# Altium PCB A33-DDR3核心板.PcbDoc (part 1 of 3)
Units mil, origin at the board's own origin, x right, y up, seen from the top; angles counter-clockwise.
Board outline 2370 x 2515 mil, 4 copper layers (TOP, GND02, PWR03, BOTTOM), stack 38.4 mil thick; 39 components, 64 nets, 546 pads, 403 vias.
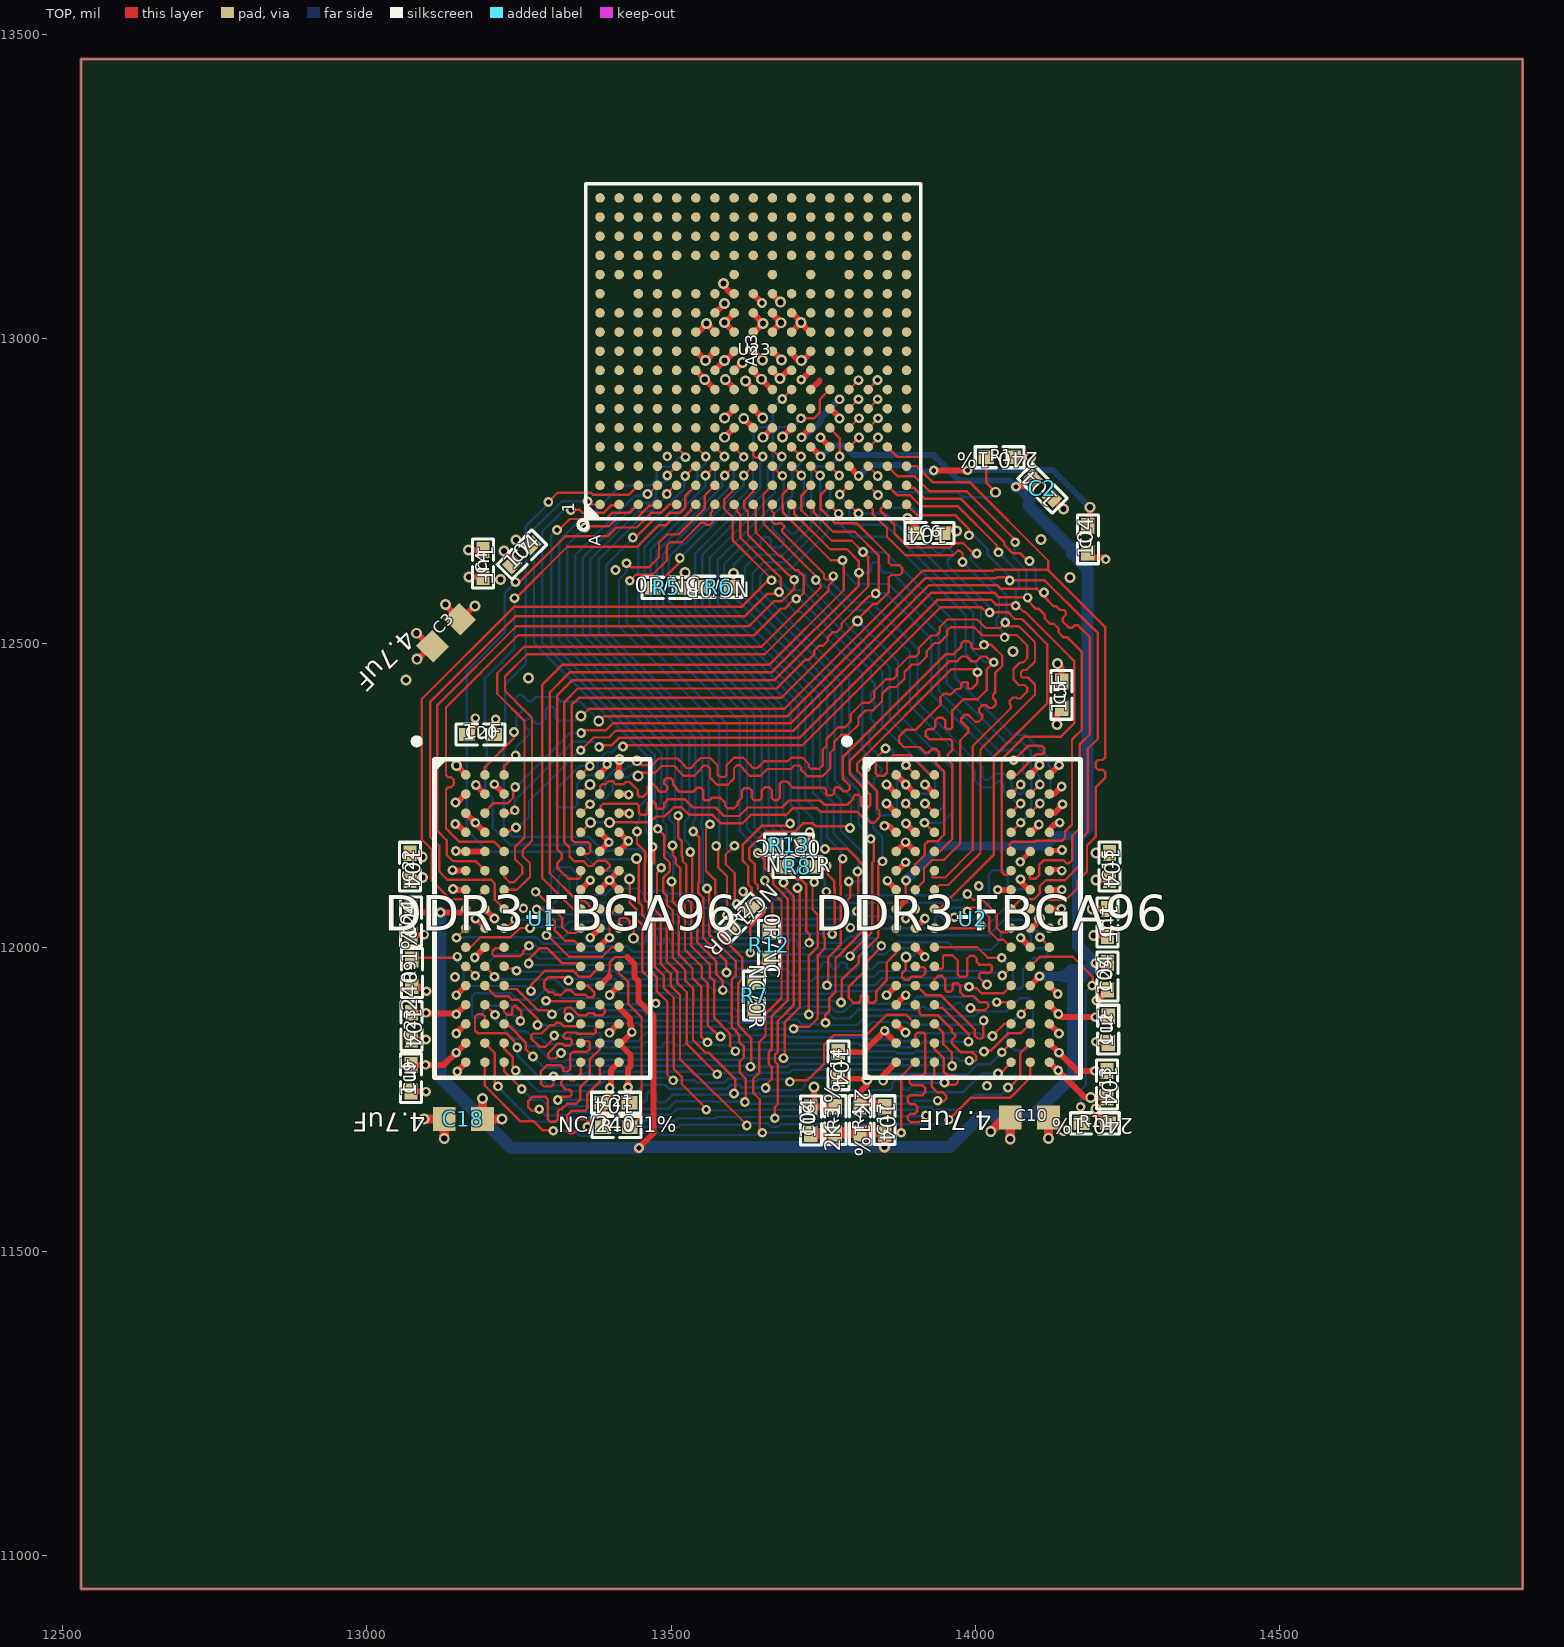
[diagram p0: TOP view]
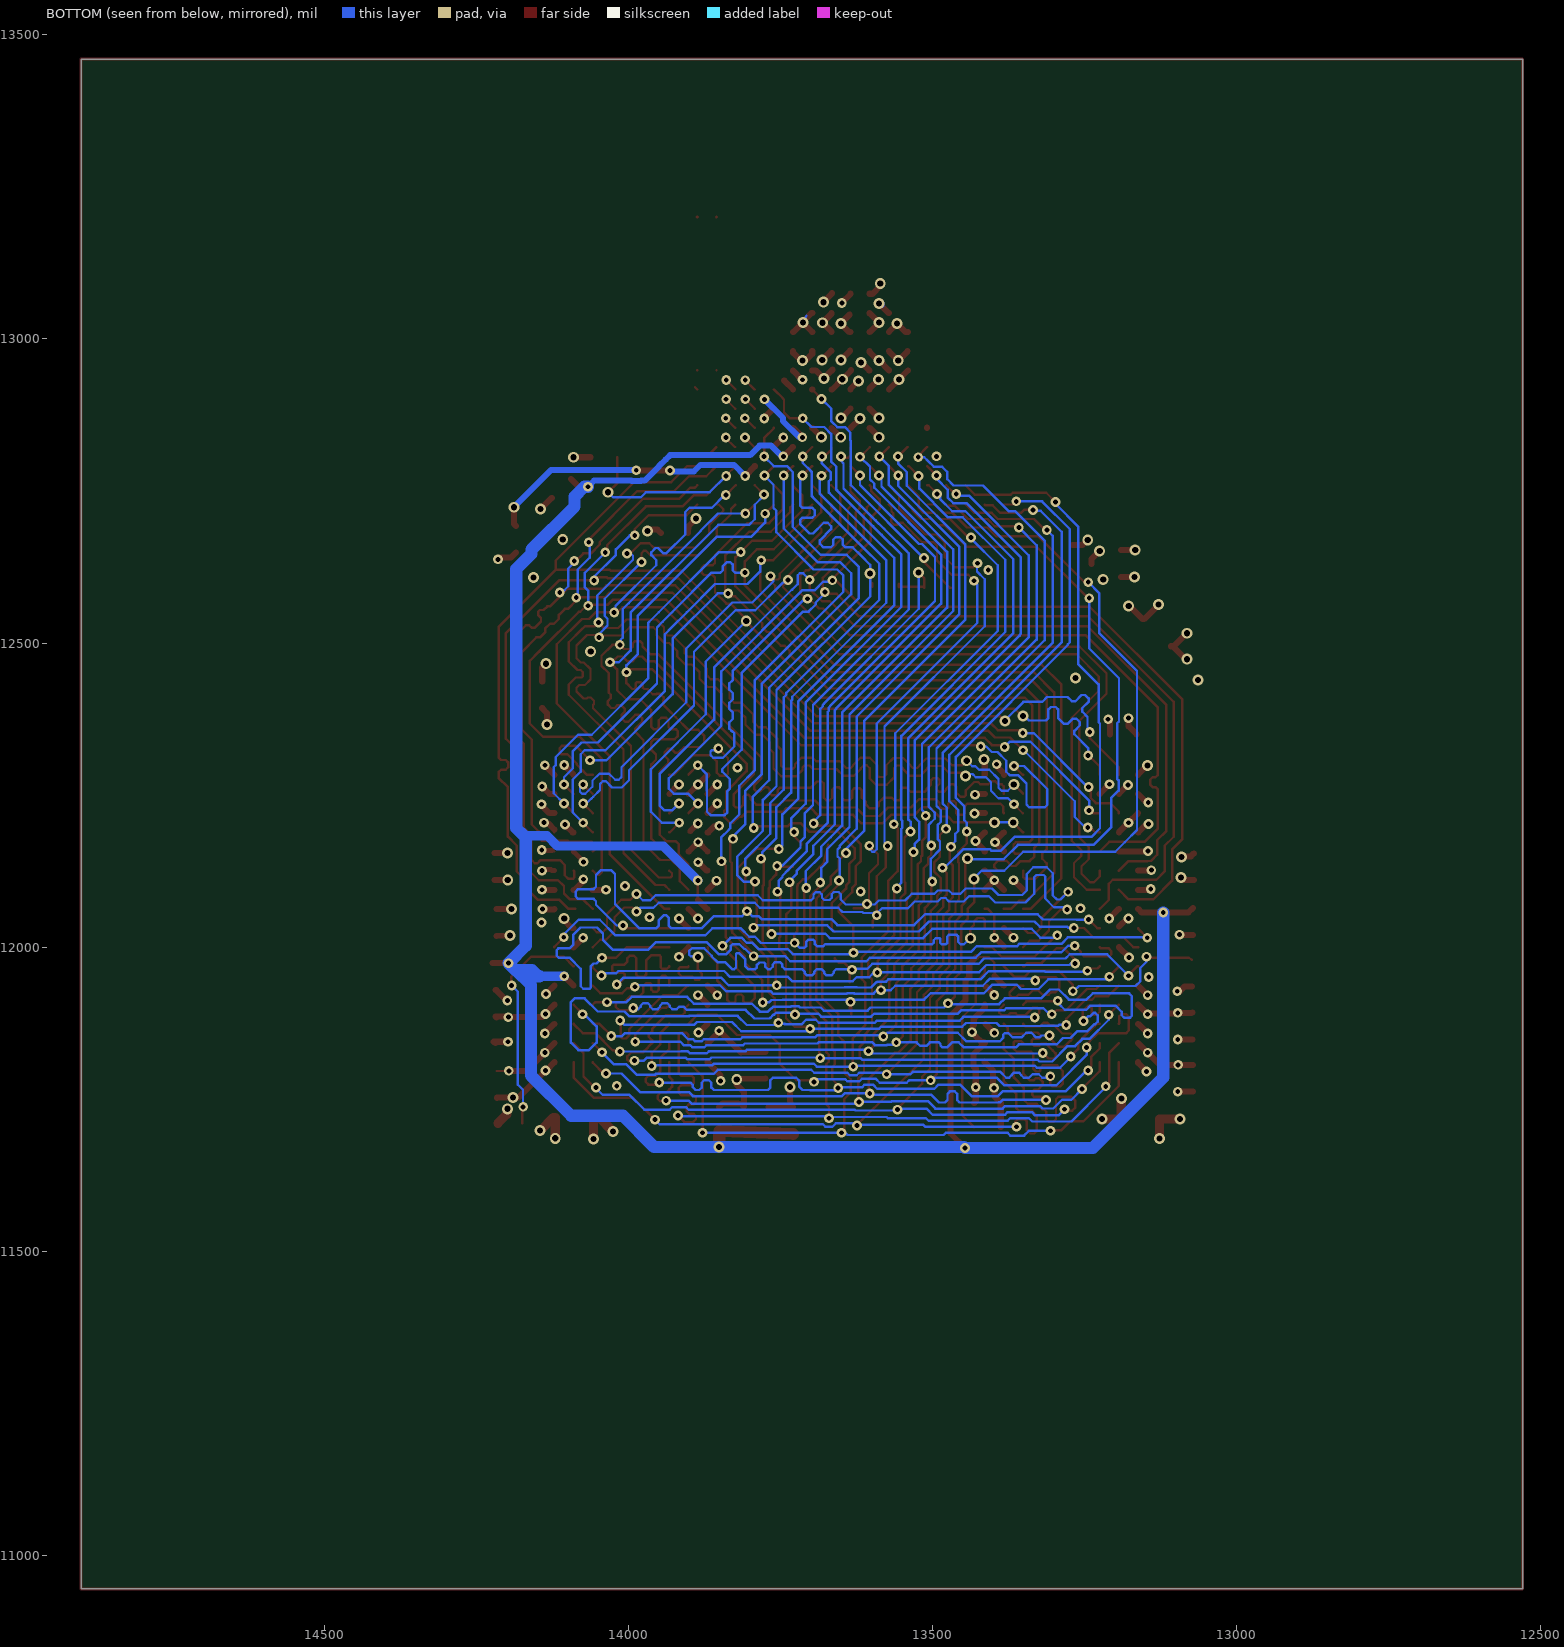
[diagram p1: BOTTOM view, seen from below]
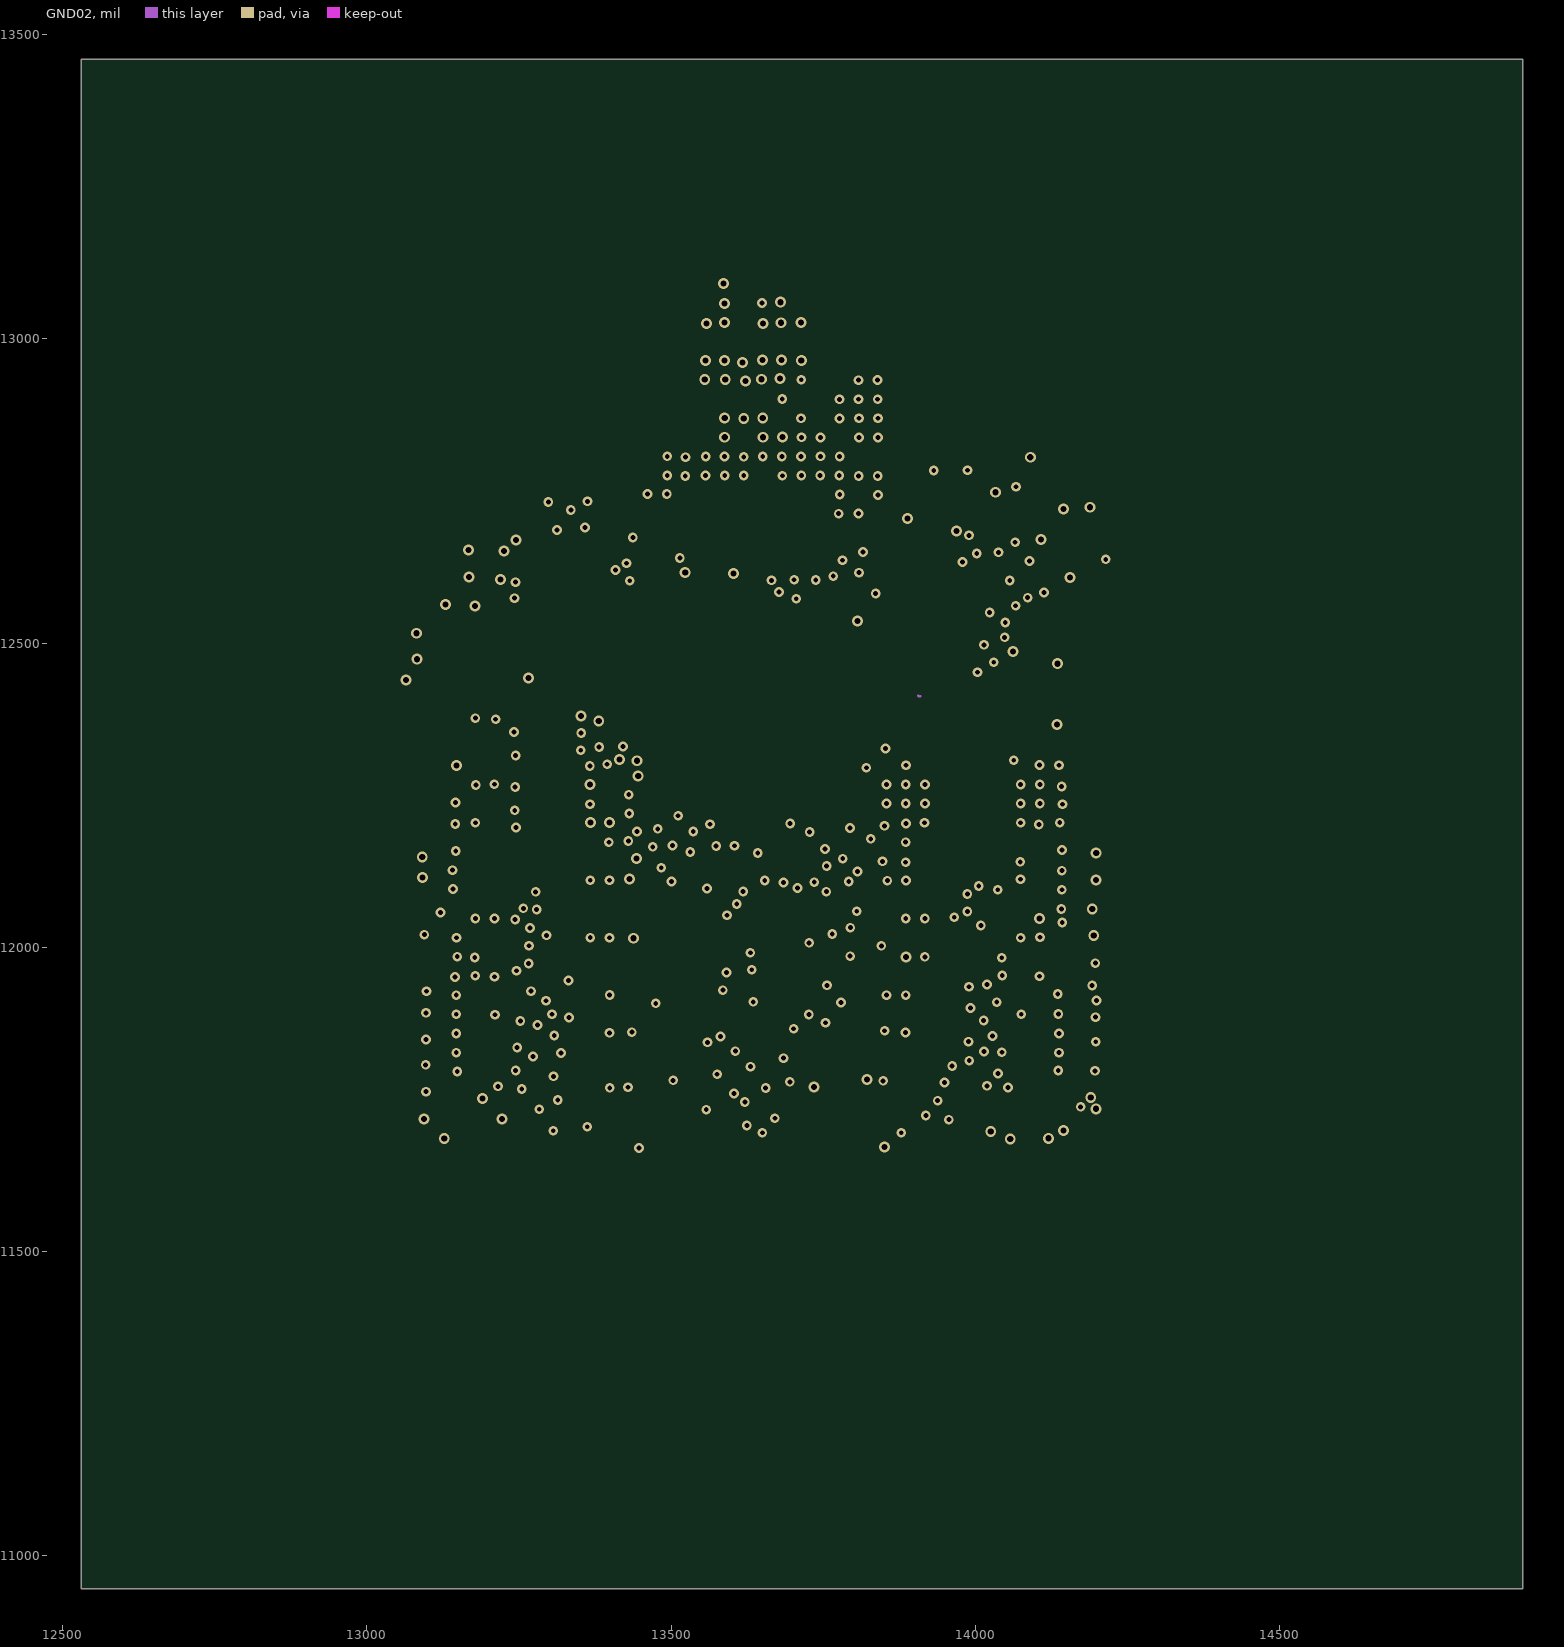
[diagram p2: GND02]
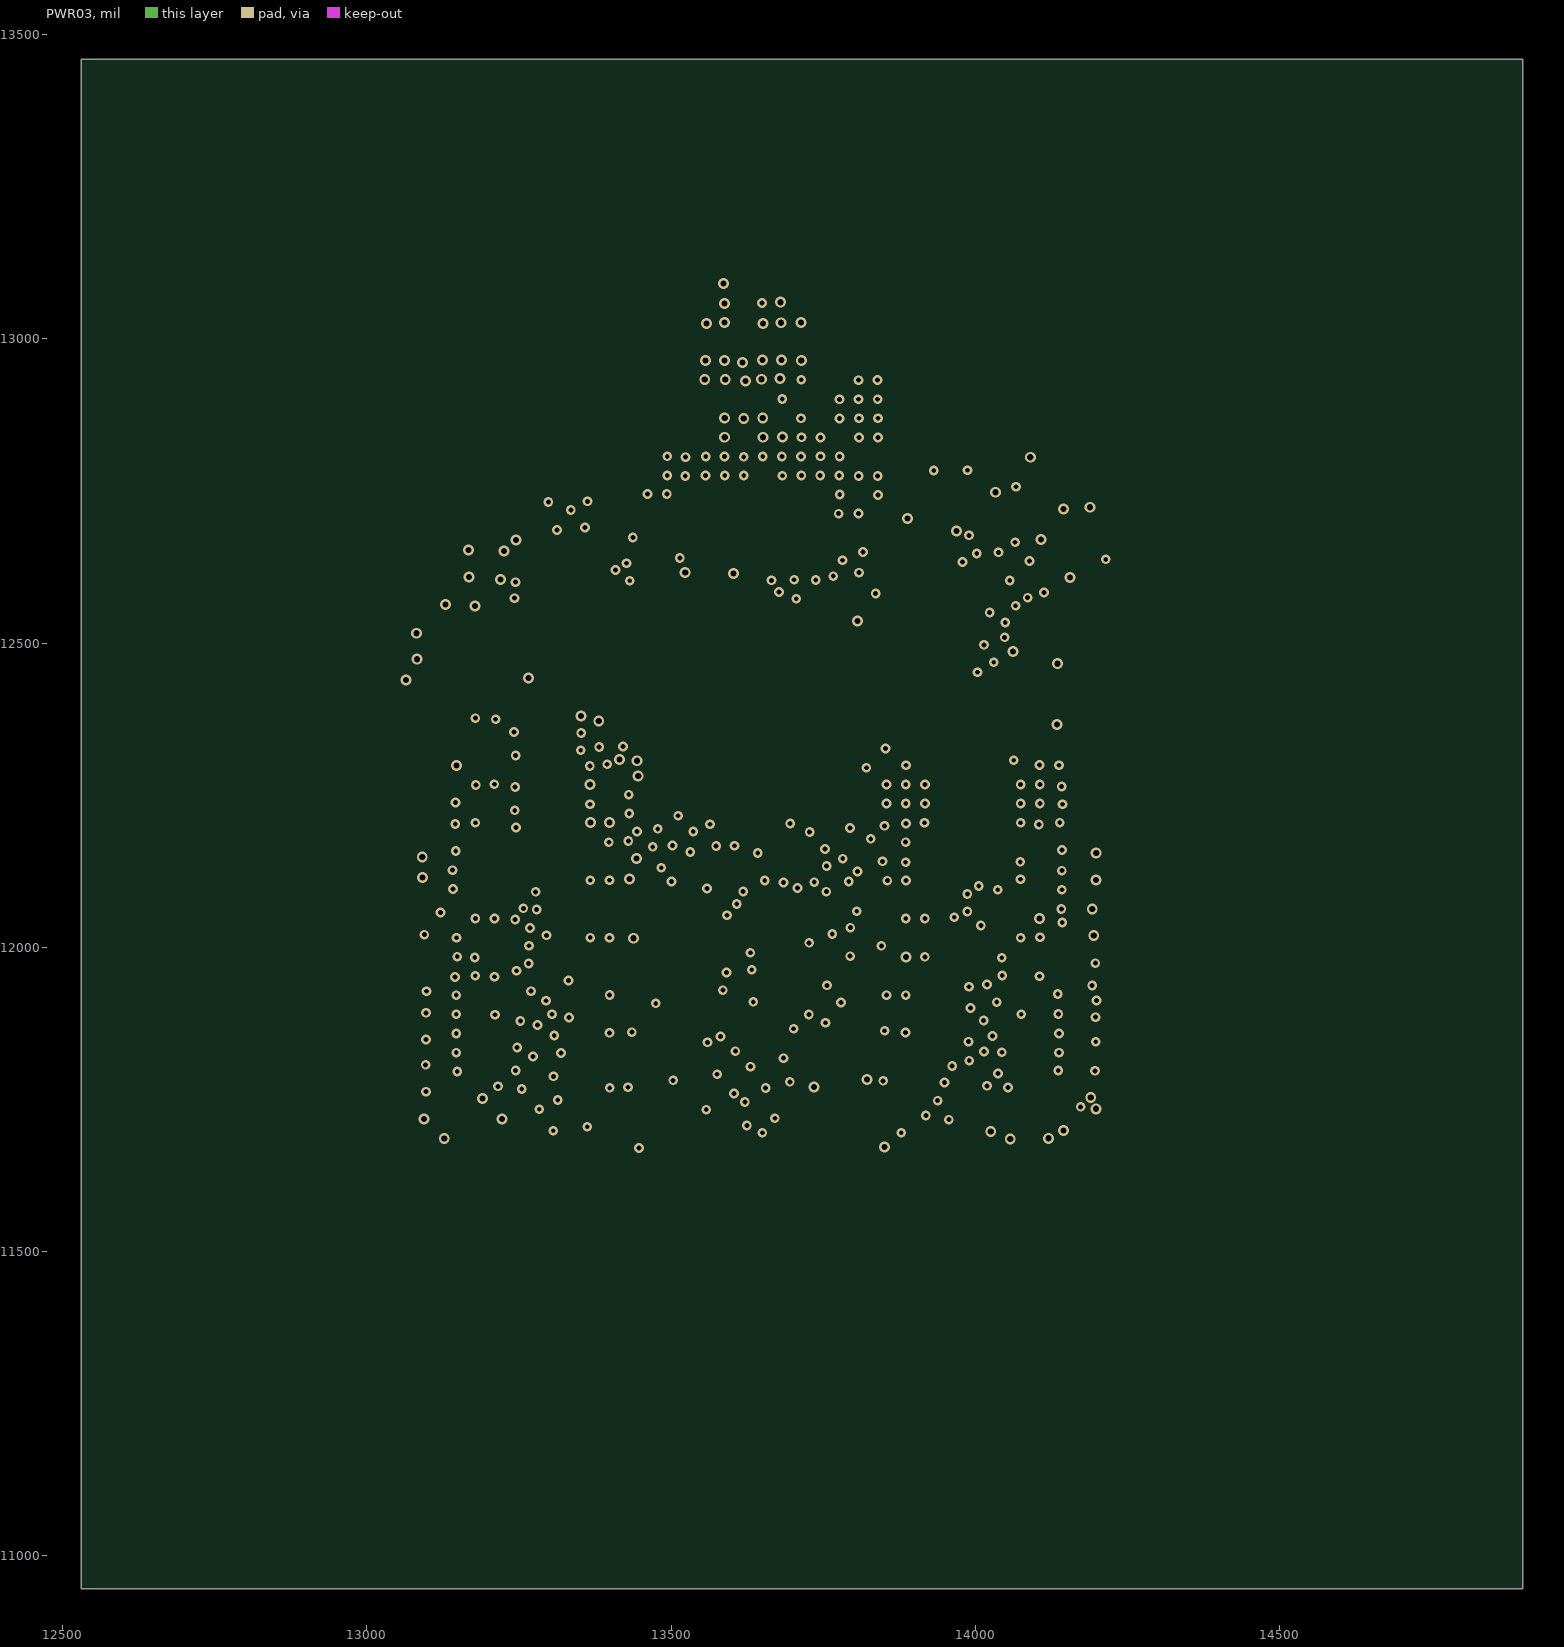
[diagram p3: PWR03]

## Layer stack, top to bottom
TOP: signal copper 1.6
Dielectric: core 2.9, FR-4, Dk 4.5
GND02: signal copper 1.2
Dielectric: core 27, FR-4, Dk 4.5
PWR03: signal copper 1.2
Dielectric: core 2.9, FR-4, Dk 4.5
BOTTOM: signal copper 1.6

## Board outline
12530,10945 12530,13460 14900,13460 14900,10945

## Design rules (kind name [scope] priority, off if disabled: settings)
Clearance [All] p1: gap=10
PlaneConnect [All] p1: planeconnectstyle=Direct reliefexpansion=20 reliefentries=4 reliefconductorwidth=10 reliefairgap=10
PolygonConnect [All] p1: connectstyle=Direct reliefconductorwidth=10 reliefentries=4 polygonreliefangle="90 Angle"
RoutingVias [All] p1: holewidth=28 width=50 viastyle="Through Hole" minholewidth=28 minwidth=50 maxholewidth=28 maxwidth=50
SilkscreenOverComponentPads SilkToSolderMaskClearance [IsPad] p1: minsilkscreentomaskgap=10
SolderMaskExpansion [All] p1: expansion=4
Width [All] p1: maxlimit=10 minlimit=10 preferedwidth=10 impedancedriven=TRUE minimp=2.160000 maximp=48.440000 favimp=2.060000
26 further rules are at their usual default settings.

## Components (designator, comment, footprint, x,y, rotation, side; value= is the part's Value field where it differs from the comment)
C1 "CAPACITOR_0_C0402_104" C0402 14185.25,12670.55 r90 top
C2 "CAPACITOR_0_C0402_104" C0402 14110.49,12754.23 r135 top
C3 "CAPACITOR_0_C0603_4.7UF" C0603 13130.2,12516.98 r225 top
C4 "CAPACITOR_0_C0402_1UF" C0402 13190.73,12630.78 r270 top
C5 "CAPACITOR_0_C0402_1UF" C0402 14141.93,12414.87 r90 top
C6 "CAPACITOR_0_C0402_104" C0402 13924.63,12680.77 r180 top
C7 "CAPACITOR_0_C0402_104" C0402 13254.63,12645.41 r45 top
C10 "CAPACITOR_0_C0603_4.7UF" C0603 14089.03,11720.11 r180 top
C11 "CAPACITOR_0_C0402_1UF" C0402 14217.37,12040.59 r270 top
C12 "CAPACITOR_0_C0402_1UF" C0402 14218.69,11864.32 r90 top
C13 "CAP_0_C0402_104" C0402 14216.52,11774.39 r270 top
C14 "CAP_0_C0402_104" C0402 13775.06,11805.81 r270 top
C15 "CAP_0_C0402_104" C0402 14220.62,12132.68 r270 top
C16 "CAPACITOR_0_C0402_104" C0402 13729.74,11714.88 r90 top
C17 "CAPACITOR_0_C0402_104" C0402 13851.01,11715.57 r270 top
C18 "CAPACITOR_0_C0603_4.7UF" C0603 13158.49,11717.8 r180 top
C19 "CAPACITOR_0_C0402_1UF" C0402 13072.42,11784.51 r90 top
C20 "CAPACITOR_0_C0402_1UF" C0402 13186.65,12349.73 r0 top
C21 "CAP_0_C0402_104" C0402 13409.35,11744.2 r180 top
C22 "CAP_0_C0402_104" C0402 13070.7,12132.27 r270 top
C23 "CAP_0_C0402_104" C0402 13073.14,11870.3 r270 top
C24 "CAPACITOR_0_C0402_104" C0402 13072.35,12042.25 r90 top
C25 "CAPACITOR_0_C0402_104" C0402 14217.33,11951.85 r90 top
R1 "R_R0402_240-1%" R0402 14040.23,12805.45 r180 top
R2 "R1 0805_R0402_NC/100R" R0402 13614.28,12048.28 r225 top
R3 "?_0_R0402_2K-1%" R0402 13769.95,11715.57 r90 top
R4 "?_0_R0402_2K-1%" R0402 13810.48,11715.91 r270 top
R5 "R1 0805_R0402_0R/NC" R0402 13492.2,12590.8 r0 top
R6 "R1 0805_R0402_NC/0R" R0402 13577.1,12592.54 r180 top
R7 "R1 0805_R0402_NC/0R" R0402 13636.45,11920.25 r270 top
R8 "R1 0805_R0402_NC/0R" R0402 13707.74,12131.95 r0 top
R9 "R_R0402_240-1%" R0402 13073.82,11957.62 r90 top
R10 "R_R0402_NC/240-1%" R0402 13410.09,11704.12 r0 top
R11 "R_R0402_240-1%" R0402 14196.47,11710.43 r180 top
R12 "R1 0805_R0402_0R/NC" R0402 13661.2,12003.64 r270 top
R13 "R1 0805_R0402_0R/NC" R0402 13694.03,12168.45 r180 top
U1 "DDR3_1_FBGA96C80P9X13_DDR3-FBGA" FBGA96C80P9X13 13288.36,12047.08 r0 top
U2 "DDR3_1_FBGA96C80P9X13_DDR3-FBGA" FBGA96C80P9X13 13995.92,12047.09 r0 top
U23 "BGA280_3_BGA282P0_80B14X14H1_30" BGA282P0_80B14X14H1_30 13635.26,12979.4 r90 top

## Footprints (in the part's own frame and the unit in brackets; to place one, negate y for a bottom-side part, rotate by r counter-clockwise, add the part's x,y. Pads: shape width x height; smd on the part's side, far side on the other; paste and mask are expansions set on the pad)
BGA282P0_80B14X14H1_30 [mm] "BGA282P0_80B14X14H1_30"
  round 0.4 smd: A1(-6.39,6.405) A2(-5.59,6.405) A3(-4.79,6.405) A4(-3.99,6.405) A5(-3.19,6.405) A6(-2.39,6.405) A7(-1.59,6.405) A8(-0.79,6.405) A9(0.01,6.405) A10(0.81,6.405) A11(1.61,6.405) A12(2.41,6.405) A13(3.21,6.405) A14(4.01,6.405) A15(4.81,6.405) A16(5.61,6.405) A17(6.41,6.405) B1(-6.39,5.605) B2(-5.59,5.605) B3(-4.79,5.605) B4(-3.99,5.605) B5(-3.19,5.605) B6(-2.39,5.605) B7(-1.59,5.605) B8(-0.79,5.605) B9(0.01,5.605) B10(0.81,5.605) B11(1.61,5.605) B13(3.21,5.605) B14(4.01,5.605) B15(4.81,5.605) B16(5.61,5.605) B17(6.41,5.605) C1(-6.39,4.805) C2(-5.59,4.805) C3(-4.79,4.805) C4(-3.99,4.805) C5(-3.19,4.805) C6(-2.39,4.805) C7(-1.59,4.805) C8(-0.79,4.805) C9(0.01,4.805) C10(0.81,4.805) C11(1.61,4.805) C12(2.41,4.805) C13(3.21,4.805) C14(4.01,4.805) C15(4.81,4.805) C16(5.61,4.805) C17(6.41,4.805) D1(-6.39,4.005) D2(-5.59,4.005) D3(-4.79,4.005) D4(-3.99,4.005) D5(-3.19,4.005) D6(-2.39,4.005) D7(-1.59,4.005) D8(-0.79,4.005) D9(0.01,4.005) D10(0.81,4.005) D11(1.61,4.005) D12(2.41,4.005) D13(3.21,4.005) D14(4.01,4.005) D15(4.81,4.005) D16(5.61,4.005) D17(6.41,4.005) E1(-6.39,3.205) E2(-5.59,3.205) E3(-4.79,3.205) E4(-3.99,3.205) E5(-3.19,3.205) E6(-2.39,3.205) E7(-1.59,3.205) E8(-0.79,3.205) E9(0.01,3.205) E10(0.81,3.205) E11(1.61,3.205) E12(2.41,3.205) E14(4.01,3.205) E15(4.81,3.205) E16(5.61,3.205) E17(6.41,3.205) F1(-6.39,2.405) F2(-5.59,2.405) F3(-4.79,2.405) F4(-3.99,2.405) F5(-3.19,2.405) F6(-2.39,2.405) F7(-1.59,2.405) F8(-0.79,2.405) F9(0.01,2.405) F10(0.81,2.405) F11(1.61,2.405) F12(2.41,2.405) F14(4.01,2.405) F15(4.81,2.405) F16(5.61,2.405) F17(6.41,2.405) G1(-6.39,1.605) G2(-5.59,1.605) G3(-4.79,1.605) G4(-3.99,1.605) G5(-3.19,1.605) G6(-2.39,1.605) G7(-1.59,1.605) G8(-0.79,1.605) G9(0.01,1.605) G10(0.81,1.605) G11(1.61,1.605) G12(2.41,1.605) G14(4.01,1.605) G15(4.81,1.605) G16(5.61,1.605) G17(6.41,1.605) H1(-6.39,0.805) H2(-5.59,0.805) H3(-4.79,0.805) H4(-3.99,0.805) H5(-3.19,0.805) H6(-2.39,0.805) H7(-1.59,0.805) H8(-0.79,0.805) H9(0.01,0.805) H10(0.81,0.805) H11(1.61,0.805) H12(2.41,0.805) H13(3.21,0.805) H14(4.01,0.805) H15(4.81,0.805) H16(5.61,0.805) H17(6.41,0.805) J1(-6.39,0.005) J2(-5.59,0.005) J3(-4.79,0.005) J4(-3.99,0.005) J5(-3.19,0.005) J6(-2.39,0.005) J7(-1.59,0.005) J8(-0.79,0.005) J9(0.01,0.005) J10(0.81,0.005) J11(1.61,0.005) J12(2.41,0.005) J14(4.01,0.005) J15(4.81,0.005) J16(5.61,0.005) J17(6.41,0.005) K1(-6.39,-0.795) K2(-5.59,-0.795) K3(-4.79,-0.795) K4(-3.99,-0.795) K5(-3.19,-0.795) K6(-2.39,-0.795) K7(-1.59,-0.795) K8(-0.79,-0.795) K9(0.01,-0.795) K10(0.81,-0.795) K11(1.61,-0.795) K12(2.41,-0.795) K13(3.21,-0.795) K14(4.01,-0.795) K15(4.81,-0.795) K16(5.61,-0.795) K17(6.41,-0.795) L1(-6.39,-1.595) L2(-5.59,-1.595) L3(-4.79,-1.595) L4(-3.99,-1.595) L5(-3.19,-1.595) L6(-2.39,-1.595) L7(-1.59,-1.595) L8(-0.79,-1.595) L9(0.01,-1.595) L10(0.81,-1.595) L11(1.61,-1.595) L12(2.41,-1.595) L14(4.01,-1.595) L15(4.81,-1.595) L16(5.61,-1.595) L17(6.41,-1.595) M1(-6.39,-2.395) M2(-5.59,-2.395) M3(-4.79,-2.395) M4(-3.99,-2.395) M5(-3.19,-2.395) M6(-2.39,-2.395) M7(-1.59,-2.395) M8(-0.79,-2.395) M9(0.01,-2.395) M10(0.81,-2.395) M11(1.61,-2.395) M12(2.41,-2.395) M13(3.21,-2.395) M14(4.01,-2.395) M15(4.81,-2.395) M16(5.61,-2.395) M17(6.41,-2.395) N1(-6.39,-3.195) N2(-5.59,-3.195) N3(-4.79,-3.195) N4(-3.99,-3.195) N5(-3.19,-3.195) N6(-2.39,-3.195) N7(-1.59,-3.195) N8(-0.79,-3.195) N9(0.01,-3.195) N10(0.81,-3.195) N11(1.61,-3.195) N12(2.41,-3.195) N14(4.01,-3.195) N15(4.81,-3.195) N16(5.61,-3.195) N17(6.41,-3.195) P1(-6.39,-3.995) P2(-5.59,-3.995) P3(-4.79,-3.995) P4(-3.99,-3.995) P5(-3.19,-3.995) P6(-2.39,-3.995) P7(-1.59,-3.995) P8(-0.79,-3.995) P9(0.01,-3.995) P10(0.81,-3.995) P11(1.61,-3.995) P12(2.41,-3.995) P13(3.21,-3.995) P14(4.01,-3.995) P15(4.81,-3.995) P16(5.61,-3.995) P17(6.41,-3.995) R1(-6.39,-4.795) R2(-5.59,-4.795) R3(-4.79,-4.795) R4(-3.99,-4.795) R5(-3.19,-4.795) R6(-2.39,-4.795) R7(-1.59,-4.795) R8(-0.79,-4.795) R9(0.01,-4.795) R10(0.81,-4.795) R11(1.61,-4.795) R12(2.41,-4.795) R13(3.21,-4.795) R14(4.01,-4.795) R15(4.81,-4.795) R16(5.61,-4.795) R17(6.41,-4.795) T1(-6.39,-5.595) T2(-5.59,-5.595) T3(-4.79,-5.595) T4(-3.99,-5.595) T5(-3.19,-5.595) T6(-2.39,-5.595) T7(-1.59,-5.595) T8(-0.79,-5.595) T9(0.01,-5.595) T10(0.81,-5.595) T11(1.61,-5.595) T12(2.41,-5.595) T13(3.21,-5.595) T14(4.01,-5.595) T15(4.81,-5.595) T16(5.61,-5.595) T17(6.41,-5.595) U1(-6.39,-6.395) U2(-5.59,-6.395) U3(-4.79,-6.395) U4(-3.99,-6.395) U5(-3.19,-6.395) U6(-2.39,-6.395) U7(-1.59,-6.395) U8(-0.79,-6.395) U9(0.01,-6.395) U10(0.81,-6.395) U11(1.61,-6.395) U12(2.41,-6.395) U13(3.21,-6.395) U14(4.01,-6.395) U15(4.81,-6.395) U16(5.61,-6.395) U17(6.41,-6.395)
  silkscreen extent -7.44,-7 7.01,7.32
C0402 [mil] "C0402"
  rect 26x22 smd: 1(-22,0) 2(22,0)
  silkscreen extent -40,-17 40,17
C0603 [mm] "C0603"
  rect 0.95x1 smd: 1(-0.8,0) 2(0.8,0)
FBGA96C80P9X13 [mm] "FBGA96C80P9X13"
  round 0.4 smd: A1(-3.2,6) A2(-2.4,6) A3(-1.6,6) A7(1.6,6) A8(2.4,6) A9(3.2,6) B1(-3.2,5.2) B2(-2.4,5.2) B3(-1.6,5.2) B7(1.6,5.2) B8(2.4,5.2) B9(3.2,5.2) C1(-3.2,4.4) C2(-2.4,4.4) C3(-1.6,4.4) C7(1.6,4.4) C8(2.4,4.4) C9(3.2,4.4) D1(-3.2,3.6) D2(-2.4,3.6) D3(-1.6,3.6) D7(1.6,3.6) D8(2.4,3.6) D9(3.2,3.6) E1(-3.2,2.8) E2(-2.4,2.8) E3(-1.6,2.8) E7(1.6,2.8) E8(2.4,2.8) E9(3.2,2.8) F1(-3.2,2) F2(-2.4,2) F3(-1.6,2) F7(1.6,2) F8(2.4,2) F9(3.2,2) G1(-3.2,1.2) G2(-2.4,1.2) G3(-1.6,1.2) G7(1.6,1.2) G8(2.4,1.2) G9(3.2,1.2) H1(-3.2,0.4) H2(-2.4,0.4) H3(-1.6,0.4) H7(1.6,0.4) H8(2.4,0.4) H9(3.2,0.4) J1(-3.2,-0.4) J2(-2.4,-0.4) J3(-1.6,-0.4) J7(1.6,-0.4) J8(2.4,-0.4) J9(3.2,-0.4) K1(-3.2,-1.2) K2(-2.4,-1.2) K3(-1.6,-1.2) K7(1.6,-1.2) K8(2.4,-1.2) K9(3.2,-1.2) L1(-3.2,-2) L2(-2.4,-2) L3(-1.6,-2) L7(1.6,-2) L8(2.4,-2) L9(3.2,-2) M1(-3.2,-2.8) M2(-2.4,-2.8) M3(-1.6,-2.8) M7(1.6,-2.8) M8(2.4,-2.8) M9(3.2,-2.8) N1(-3.2,-3.6) N2(-2.4,-3.6) N3(-1.6,-3.6) N7(1.6,-3.6) N8(2.4,-3.6) N9(3.2,-3.6) P1(-3.2,-4.4) P2(-2.4,-4.4) P3(-1.6,-4.4) P7(1.6,-4.4) P8(2.4,-4.4) P9(3.2,-4.4) R1(-3.2,-5.2) R2(-2.4,-5.2) R3(-1.6,-5.2) R7(1.6,-5.2) R8(2.4,-5.2) R9(3.2,-5.2) T1(-3.2,-6) T2(-2.4,-6) T3(-1.6,-6) T7(1.6,-6) T8(2.4,-6) T9(3.2,-6)
  silkscreen extent -5.37,-6.65 4.5,7.52
R0402 [mil] "R0402"
  rect 26x22 smd: 1(-22,0) 2(22,0)
  silkscreen extent -40,-17 40,17

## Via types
v1: diameter 16, hole 8, TOP to BOTTOM, 320 vias
v2: diameter 18, hole 10, TOP to BOTTOM, 83 vias

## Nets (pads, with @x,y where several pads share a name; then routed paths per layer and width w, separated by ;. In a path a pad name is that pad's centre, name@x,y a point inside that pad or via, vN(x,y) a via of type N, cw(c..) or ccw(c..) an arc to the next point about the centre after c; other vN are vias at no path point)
DA0: U1.N3 U2.N3 U23.E4 | length 2241
  TOP w4: U1.N3@13225.37,11905.35 13225.37,11893.91 13230.65,11888.63 13237.02,11888.63 13238.66,11890.27 13238.66,11899.49 13242.75,11903.58 13244.7,11903.58 13253.34,11894.94 13253.34,11879.8 v1(13252.13,11878.59) ; v1(13500.77,12107.93) 13502.53,12106.17 13502.53,12074.98 13512.85,12064.65 13512.85,11987.66 13535.18,11965.33 13535.18,11949.22 13549.18,11935.22 13549.18,11853.19 13558.81,11843.56 v1(13559.81,11843.56) ; U23.E4@13509.07,12822.31 13523.68,12807.71 13523.68,12805.73 v1(13523.81,12805.6) ; U2.N3@13932.93,11905.36 13937.75,11900.53 13945.56,11900.53 13989.03,11857.07 v1(13989.03,11844.67)
  BOTTOM w4: v1(13252.13,11878.59) 13244.54,11886.17 13241.44,11886.17 13235.55,11892.06 13232.94,11892.06 13228.92,11888.04 13228.92,11877.47 13232.79,11873.6 13234.08,11873.6 13245.74,11861.95 13261.92,11861.95 13273.23,11850.64 13285.57,11850.64 13296.13,11840.08 13358.23,11840.08 13363.15,11835.16 13448.79,11835.16 13457.19,11843.56 13467.94,11843.56 13476.34,11835.16 13484.09,11835.16 13487.12,11838.19 13487.12,11840.8 13489.89,11843.56 13504.53,11843.56 13510.36,11837.73 13520.53,11837.73 13526.36,11843.56 v1(13559.81,11843.56) 13563.88,11839.49 13574.77,11839.49 13575.24,11839.02 13594.91,11839.02 13599.87,11843.99 13686.88,11843.99 13689.18,11841.68 13808.96,11841.68 13812.07,11838.57 13872.17,11838.57 13875.19,11835.55 13895.08,11835.55 13898.1,11838.57 13908.94,11838.57 13915.04,11844.67 v1(13989.03,11844.67) ; v1(13500.77,12107.93) 13503.27,12110.43 13503.27,12145.04 13487.99,12160.33 13487.99,12174 13491.99,12178 13491.99,12200.82 13486.59,12206.21 13486.59,12220.26 13486.64,12220.31 13486.64,12225.18 13493.75,12232.29 13493.75,12326.75 13315.98,12504.53 13315.98,12668.61 13363.86,12716.49 13374.67,12716.49 13417.24,12759.06 13465.62,12759.06 13476.11,12769.54 13476.11,12781.3 13484.61,12789.8 13498.1,12789.8 13507.53,12799.23 13513.76,12805.46 13523.68,12805.46 v1(13523.81,12805.6)
DA1: U1.P7 U2.P7 U23.D1 | length 2054
  TOP w4: v1(13307.79,11854.81) 13307.79,11850.75 13293.15,11836.11 13284.17,11836.11 13274.25,11846.03 13273.58,11846.03 13270.24,11849.37 13270.24,11855.03 13273.28,11858.08 13286.97,11858.08 13300.59,11871.69 13307.41,11871.69 13311.79,11876.07 13317.45,11876.07 13323.85,11869.67 13347.16,11869.67 U1.P7@13351.35,11873.86 ; v1(13358.34,12689.95) 13360.31,12691.92 13397.95,12691.92 13409.98,12703.95 13442.04,12703.95 13451.83,12713.74 13451.83,12713.95 13463.43,12725.54 13475.3,12725.54 U23.D1@13477.58,12727.82 ; v1(13502.35,12167.16) 13502.35,12151.97 13507.69,12146.64 13507.69,12136.96 13514.77,12129.88 13514.77,12076.88 13522.85,12068.79 13522.85,11995.62 13550.36,11968.11 13550.36,11950.44 13560.01,11940.78 13560.01,11872.34 13579.33,11853.02 v1(13581.12,11853.02) ; v1(14028.47,11853.87) 14028.47,11854.61 14047.72,11873.86 U2.P7@14058.91,11873.86
  BOTTOM w4: v1(13307.79,11854.81) 13321.32,11854.81 13324.56,11851.57 13330.19,11851.57 13337.83,11859.21 13346.19,11859.21 13353.83,11851.57 13368.39,11851.57 13375.66,11858.84 13381.32,11858.84 13384.15,11856.01 13384.15,11850.83 13389.81,11845.16 13444.65,11845.16 13458.82,11859.33 13574.53,11859.33 13580.83,11853.02 v1(13581.12,11853.02) 13581.41,11853.02 13583.93,11855.54 13689.47,11855.54 13693.32,11851.68 13813.1,11851.68 13816.21,11848.57 13876.31,11848.57 13879.34,11845.55 13890.93,11845.55 13893.96,11848.57 13902.08,11848.57 13912.17,11858.67 14006.11,11858.67 14010.9,11853.87 v1(14028.47,11853.87) ; v1(13358.34,12689.95) 13329.19,12660.8 13329.19,12505.77 13506.33,12328.62 13506.33,12230.74 13497.51,12221.92 13497.51,12221.57 13496.64,12220.69 13496.64,12211.08 13506.15,12201.57 13506.15,12170.96 v1(13502.35,12167.16)
DA2: U1.P3 U2.P3 U23.F2 | length 2009.9
  TOP w4: U1.P3@13225.37,11873.86 13230,11873.86 13233.69,11870.17 13234.15,11870.17 13260.82,11843.51 13260.82,11832.47 13272.97,11820.32 v1(13272.97,11820.19) ; v1(13437.08,12673.41) 13438.91,12675.24 13442.93,12675.24 13471.64,12703.95 13487.47,12703.95 13497.47,12713.95 13514.82,12713.95 13522.95,12722.08 13522.95,12741.7 U23.F2@13540.57,12759.32 ; v1(13563.81,12202.06) 13557.33,12195.58 13557.33,12125.1 13572.85,12109.58 13572.85,12026.53 13616.63,11982.75 13616.63,11947.38 13610.54,11941.29 13610.54,11872.05 13617.27,11865.32 13617.27,11864.45 13621.84,11859.88 13621.84,11859.54 13631.57,11849.82 13631.57,11809.05 13630.53,11808.01 v1(13630.53,11803.54) ; U2.P3@13932.93,11873.86 13947.63,11859.16 13947.63,11840.41 13961.53,11826.51 13961.53,11805.01 v1(13962.03,11804.51)
  BOTTOM w4: v1(13272.97,11820.19) 13272.97,11819.42 13290.31,11802.08 13328.89,11802.08 13331.89,11805.07 v1@13628.99,11805.07 ; v1(13437.08,12673.41) 13435.25,12671.58 13435.25,12670.14 13393.08,12627.97 13393.08,12520.05 13561.52,12351.6 13561.52,12204.34 v1(13563.81,12202.06) ; v1@13628.16,11805.91 v1@13628.99,11805.07 ; v1(13962.03,11804.51) 13960.99,11805.55 13862.77,11805.55 13859.75,11808.57 13695.62,11808.57 13690.58,11803.54 v1(13630.53,11803.54) v1@13628.99,11805.07
DA3: U1.N2 U2.N2 U23.H3 | length 2159.7
  TOP w4: U1.N2@13193.87,11905.35 13194.48,11905.35 13210.45,11889.38 v1(13210.45,11888.9) ; v1(13588.09,12775.34) U23.H3@13603.56,12790.81 ; v1(13684.78,11817.54) 13684.78,11822.14 13686.66,11824.02 13686.66,11876.05 13711.49,11900.87 13711.49,12092.42 13707.85,12096.06 v1(13707.85,12097.37) ; U2.N2@13901.43,11905.36 13907.59,11899.2 13907.59,11892.17 13912.03,11887.73 13939.03,11887.73 13961.2,11865.57 13961.2,11861.52 13967.04,11855.68 13967.04,11852.68 13961.2,11846.84 13961.2,11842.26 13974.07,11829.39 ; 13974.11,11829.39 13976.53,11826.97 13995.6,11826.97 14001.87,11820.7 14001.87,11815.04 13999.09,11812.27 13991.23,11812.27 v1(13990.04,11813.46)
  BOTTOM w4: v1(13210.45,11888.9) 13210.45,11880.66 13241.98,11849.13 13253.9,11849.13 13265.8,11837.22 13278.32,11837.22 13303.47,11812.08 13324.75,11812.08 13327.74,11815.07 13616.06,11815.07 13618.52,11817.54 v1(13684.78,11817.54) 13685.82,11818.57 13863.89,11818.57 13866.91,11815.55 13903.36,11815.55 13906.32,11818.51 13969.8,11818.51 13974.86,11813.46 v1(13990.04,11813.46) ; v1(13588.09,12775.34) 13588.09,12775.05 13584.09,12771.05 13584.09,12757.66 13476.19,12649.75 13476.19,12558.24 13648.79,12385.63 13648.79,12199.86 13667.88,12180.78 13667.88,12180.72 13683.51,12165.09 13683.51,12150.17 13708.69,12124.99 13708.69,12098.38 13707.85,12097.54 v1(13707.85,12097.37)
DA4: U1.P8 U2.P8 U23.D2 | length 2087.6
  TOP w4: v1(13318.95,11826.08) 13309.87,11817 13300.52,11817 13297.9,11819.62 13297.9,11825.27 13302.56,11829.93 13302.56,11830.25 13313.7,11841.39 13321.59,11841.39 13325.07,11837.91 13333.44,11837.91 13336.91,11841.38 13336.91,11846.91 13334.7,11849.12 13326.25,11849.12 13322.57,11852.8 13322.57,11854.84 13327.4,11859.67 13342.95,11859.67 13344.95,11857.67 13373.21,11857.67 13376.27,11860.73 13376.27,11867.28 U1.P8@13382.85,11873.86 ; v1(13461.35,12745.06) 13463.32,12745.06 U23.D2@13477.58,12759.32 ; v1(13511.51,12216.12) 13511.51,12180.49 13517.35,12174.66 13517.35,12150.62 13519.18,12148.78 13519.18,12141.22 13524.77,12135.63 13524.77,12081.02 13532.85,12072.94 13532.85,12002.45 13563.38,11971.92 13563.38,11951.56 13570.01,11944.92 13570.01,11944.36 13571.05,11943.33 13571.05,11883.26 13597.27,11857.04 13597.27,11837.38 v1(13605.57,11829.07) ; v1(14014.31,11828.51) 14021.59,11828.51 14023.36,11830.28 14026.02,11830.28 14054.4,11858.67 14075.22,11858.67 U2.P8@14090.41,11873.86
  BOTTOM w4: v1(13318.95,11826.08) 13319.87,11825.16 13597.88,11825.16 13601.8,11829.07 v1(13605.57,11829.07) 13606.1,11829.07 13608.57,11831.54 13804.96,11831.54 13807.93,11828.57 13868.03,11828.57 13871.05,11825.55 13899.22,11825.55 13902.24,11828.57 13913.55,11828.57 13913.61,11828.51 v1(14014.31,11828.51) ; v1(13461.35,12745.06) 13458.66,12742.37 13440.33,12742.37 13342.27,12644.31 13342.27,12509.15 13517.54,12333.88 13517.54,12225.72 13511.51,12219.7 v1(13511.51,12216.12)
DA5: U1.P2 U2.P2 U23.F1 | length 2327.2
  TOP w4: U1.P2@13193.87,11873.86 13193.25,11874.48 13193.25,11886.35 13189.98,11889.62 13181.65,11889.62 13177.56,11885.53 13177.56,11862.98 13182.38,11858.17 13229.18,11858.17 13241.66,11845.69 13241.66,11845.22 13246.82,11840.07 v1(13246.82,11834.89) ; v1(13242.49,12573.82) 13244.68,12573.82 13329.24,12658.37 13444.76,12658.37 13480.34,12693.95 13491.61,12693.95 13501.61,12703.95 13518.96,12703.95 13532.95,12717.93 13532.95,12720.11 13540.57,12727.73 U23.F1@13540.57,12727.82 ; v2(13442.74,12145.71) 13446.77,12141.69 13446.77,12073.93 13447.91,12072.78 13447.91,12072.57 13452.53,12067.96 13452.53,12052.79 13462.85,12042.46 13462.85,11964.18 13476.03,11951 13476.03,11928.24 13493.56,11910.72 13493.56,11790.8 v1(13503.28,11781.07) ; v1(13695.16,11778.63) 13697.68,11781.15 13724.31,11781.15 13751.29,11808.13 13751.29,11838.98 13767.91,11855.6 13821.42,11855.6 13854.98,11889.15 13886.14,11889.15 U2.P2@13901.43,11873.86
  BOTTOM w4: v1(13242.49,12573.82) 13242.49,12490.99 13193.71,12442.2 13193.71,12371.29 13196.63,12368.36 13196.63,12276.34 13194.41,12274.13 13194.41,12257.45 13206.71,12245.15 13206.71,12196.82 13235.48,12168.06 13359.8,12168.06 13383.28,12144.58 13441.61,12144.58 v2(13442.74,12145.71) ; v1(13246.82,11834.89) 13246.82,11822.8 13296.77,11772.84 13382.19,11772.84 13394.42,11785.07 13499.28,11785.07 v1(13503.28,11781.07) 13538.65,11781.07 13542.65,11777.07 13586.95,11777.07 13593.41,11783.54 13593.95,11783.54 13594.14,11783.74 13616.39,11783.74 13620.59,11779.54 13640.47,11779.54 13643.57,11782.63 13690.03,11782.63 13694.03,11778.63 v1(13695.16,11778.63)
DA6: U1.R8 U2.R8 U23.A1 | length 2394.8
  TOP w4: v1(13283.24,11733.5) 13281.15,11731.41 13270.5,11731.41 13265.43,11736.49 13265.43,11747.26 13271.96,11753.8 13293.53,11753.8 13297.28,11750.05 13297.28,11717.12 13301.28,11713.12 13309.28,11713.12 13313.28,11717.12 13313.28,11729.5 13317.28,11733.5 13320.03,11733.5 13329.22,11742.68 13343.75,11742.68 13350.48,11749.41 13350.48,11769.39 13366.53,11785.44 13366.53,11815.92 13382.85,11832.25 U1.R8@13382.85,11842.36 ; v1(13362.56,12732.99) 13367.73,12727.82 U23.A1@13383.09,12727.82 ; v1(13443.93,12190.14) 13443.93,12170.59 13457.74,12156.78 13457.74,12139.5 13456.77,12138.52 13456.77,12078.07 13457.91,12076.93 13457.91,12076.71 13462.53,12072.1 13462.53,12057.37 13472.85,12047.04 13472.85,11968.32 13488.12,11953.05 13488.12,11933.04 13504.4,11916.76 13504.4,11799.76 13517.28,11786.87 13517.28,11775.53 13557.8,11735.02 v1(13557.8,11732.85) ; v1(14053.66,11769.4) 14056.07,11769.4 14074.03,11787.36 14074.03,11825.98 U2.R8@14090.41,11842.36 ; U2.R8@14090.22,11842.36 U2.R8@14090.41,11842.36 ; U2.R8@14090.23,11842.37 U2.R8@14090.41,11842.36
  BOTTOM w4: v1(13283.24,11733.5) 13293.21,11723.52 13331.56,11723.52 13336.76,11728.73 13376.85,11728.73 13380.99,11724.58 13500.25,11724.58 13510.2,11734.54 13554.64,11734.54 13556.34,11732.85 v1(13557.8,11732.85) 13560.95,11732.85 13562.27,11731.54 13627.06,11731.54 13628.32,11732.8 13901.36,11732.8 13905.69,11737.14 13928.21,11737.14 13932.55,11732.8 13973.99,11732.8 13998.43,11757.24 14042.46,11757.24 14053.66,11768.45 v1(14053.66,11769.4) ; v1(13362.56,12732.99) 13320.15,12732.99 13274.55,12687.38 13274.55,12501.13 13277.93,12497.74 13277.93,12496.8 13461.89,12312.84 13461.89,12245.26 13447.95,12231.33 13447.95,12208.61 13443.93,12204.59 v1(13443.93,12190.14)
DA7: U1.R2 U2.R2 U23.G4 | length 2384.9
  TOP w4: U1.R2@13193.87,11842.36 13209.94,11826.3 13209.94,11776.67 v1(13215.37,11771.24) ; U23.G4@13572.07,12822.31 v1@13587.64,12806.74 ; v1(13670.5,11718.8) 13670.5,11737.1 13675.19,11741.8 13675.19,11807.32 13670.78,11811.74 13670.78,11823.34 13675.19,11827.75 13675.19,11878.72 13701.49,11905.02 13701.49,12083.26 13700.77,12083.99 13700.77,12084.54 13696.77,12088.54 13696.77,12088.82 13686.49,12099.1 13686.49,12104.78 v1(13684.87,12106.39) ; U2.R2@13901.43,11842.36 13901.56,11842.5 13901.56,11855.72 13905.32,11859.47 13914.63,11859.47 13917.53,11856.57 13917.53,11792.79 13913.53,11788.79 13896.65,11788.79 13892.65,11784.79 13892.65,11776.79 13896.65,11772.79 13913.53,11772.79 13917.53,11768.79 13917.53,11760.79 13913.53,11756.79 13892.98,11756.79 13889.07,11752.88 13889.07,11746.1 13893.07,11742.1 13900.42,11742.1 13904.42,11738.1 13904.42,11730.1 13900.42,11726.1 13893.07,11726.1 13889.07,11722.1 13889.07,11717.18 13893.8,11712.45 13908.12,11712.45 v1(13918.8,11723.14)
  BOTTOM w4: v1(13215.37,11771.24) 13217.95,11768.65 13217.95,11767.37 13271.97,11713.35 13336.39,11713.35 13341.77,11718.73 13372.71,11718.73 13376.85,11714.58 13506.92,11714.58 13511.18,11718.85 13573.55,11718.85 13575.53,11720.82 13668.47,11720.82 v1(13670.5,11718.8) 13673.62,11721.93 13914.6,11721.93 13915.81,11723.14 v1(13918.8,11723.14) ; v1(13587.66,12806.74) 13587.51,12806.74 13572.09,12791.32 13572.09,12759.8 13466.19,12653.9 13466.19,12552.82 13636.79,12382.22 13636.79,12197.66 13673.51,12160.95 13673.51,12140.03 13683.08,12130.46 13683.08,12109.8 13684.87,12108.01 v1(13684.87,12106.39)
DA8: U1.T8 U2.T8 U23.B1 | length 2288.8
  TOP w4: v1(13335.18,12718.79) 13349.7,12718.79 13354.54,12713.95 13388.84,12713.95 13401.3,12726.41 13413.18,12726.41 U23.B1@13414.59,12727.82 ; v1(13362.09,11704.73) 13364.35,11706.98 13364.35,11713.08 13360.72,11716.7 13348.1,11716.7 13345.05,11713.65 13345.05,11699.22 13339.51,11693.68 13332.98,11693.68 13329.06,11697.6 13329.06,11723.73 13336.33,11730.99 13358.37,11730.99 13362.37,11734.99 13362.37,11758.66 13382.85,11779.13 U1.T8@13382.85,11810.86 ; v1(13469.7,12164.97) 13472.23,12162.43 13472.23,12139.85 13466.77,12134.38 13466.77,12082.21 13467.91,12081.07 13467.91,12080.86 13472.53,12076.24 13472.53,12061.78 13482.85,12051.45 13482.85,11972.46 13499.05,11956.26 13499.05,11937.14 13514.59,11921.59 13514.59,11815.66 13530.84,11799.41 13616.13,11716.36 13624.51,11707.98 v1(13624.51,11706.82) ; v1(13956.59,11716.42) 13992.32,11752.15 14056.91,11752.15 14090.4,11785.64 14090.4,11802.15 U2.T8@14090.41,11810.87
  BOTTOM w4: v1(13335.18,12718.79) 13333.68,12717.29 13322.43,12717.29 13288.01,12682.87 13288.01,12500.86 13472.85,12316.03 13472.85,12240.15 13457.95,12225.26 13457.95,12191.2 13462.99,12186.16 13462.99,12174.14 13469.7,12167.44 v1(13469.7,12164.97) ; v1(13362.09,11704.73) 13366.72,11704.73 13366.86,11704.58 13511.99,11704.58 13515.2,11707.79 13621.01,11707.79 13621.3,11707.5 13623.84,11707.5 v1(13624.51,11706.82) 13625.18,11707.5 13626.74,11707.5 13629.47,11710.22 13659.28,11710.22 13664.7,11704.8 13676.3,11704.8 13680.3,11708.8 13948.97,11708.8 v1(13956.59,11716.42)
DA9: U1.R3 U2.R3 U23.F4 | length 2191.5
  TOP w4: U1.R3@13225.37,11842.36 13225.37,11833.45 13239.48,11819.34 13239.48,11804.7 13244.35,11799.83 v1(13244.35,11797.11) ; U23.F4@13540.57,12822.31 13541.15,12822.31 v1(13556.89,12806.56) ; v1(13642.44,12154.91) 13654.09,12143.26 13654.09,12129.21 13667.82,12115.48 13667.82,12103.62 13686.77,12084.67 13686.77,12084.39 13690.77,12080.39 13690.77,12079.84 13691.49,12079.12 13691.49,11912.34 13665.19,11886.05 13665.19,11831.89 13660.78,11827.48 13660.78,11807.59 13665.19,11803.18 13665.19,11782.8 13655.45,11773.06 v1(13655.45,11768.63) ; U2.R3@13932.93,11842.36 13932.93,11832.89 13948.03,11817.79 13948.03,11795.45 13954.57,11788.9 13966.82,11788.9 13971.67,11784.05 13971.67,11778.39 13967.31,11774.04 13952.93,11774.04 v1(13949.59,11777.37)
  BOTTOM w4: v1(13244.35,11797.11) 13247.35,11797.11 13281.65,11762.81 13385.19,11762.81 13393.31,11754.7 13435.44,11754.7 13454.29,11773.54 13491.02,11773.54 13497.49,11767.07 13591.09,11767.07 13597.55,11773.54 13612.44,11773.54 13616.45,11769.54 13654.55,11769.54 v1(13655.45,11768.63) 13659.45,11764.63 13700.96,11764.63 13701.57,11765.24 13713.99,11765.24 13719.7,11770.95 13719.7,11780.81 13724.28,11785.39 13762.7,11785.39 13766.7,11781.39 13766.7,11769.24 13770.7,11765.24 13859.74,11765.24 13863.74,11769.24 13863.74,11777.14 13867.74,11781.14 13875.74,11781.14 13879.74,11777.14 13879.74,11769.24 13883.74,11765.24 13889.82,11765.24 13894.53,11769.95 13894.53,11773.61 13898.3,11777.37 v1(13949.59,11777.37) ; v1(13556.89,12806.56) 13556.89,12795.44 13542.6,12781.14 13542.6,12758.59 13446.19,12662.18 13446.19,12538.58 13612.79,12371.98 13612.79,12190.95 13642.44,12161.31 v1(13642.44,12154.91)
DA10: U1.L7 U2.L7 U23.E2 | length 1911.1
  TOP w4: v1(13265.8,11973.25) 13265.8,11979.64 13284.68,11998.52 13296.13,11998.52 13320.82,11973.82 13344.02,11973.82 13349.5,11968.34 U1.L7@13351.35,11968.34 ; v1(13492.93,12745.17) 13492.93,12745.87 13506.38,12759.32 U23.E2@13509.07,12759.32 ; v1(13536.27,12190.27) 13546.36,12180.18 13546.36,12106.98 13544.77,12105.38 13544.77,12089.3 13552.85,12081.22 13552.85,12015.02 13590.46,11977.42 13590.46,11958.95 v1(13591.21,11958.2) ; v1(14044.32,11953.42) 14044.32,11953.81 v1@14043.06,11955.07 ; v1@14045.03,11954.67 14044.63,11955.07 v1@14043.06,11955.07 ; U2.L7@14058.91,11968.35 14058.91,11966.55 14048.62,11956.26 14044.26,11956.26 v1@14043.06,11955.07
  BOTTOM w4: v1(13265.8,11973.25) 13272.6,11973.25 13275.11,11970.74 13411.87,11970.74 13423.53,11959.08 13590.33,11959.08 v1(13591.21,11958.2) 13592.05,11958.2 13592.8,11957.45 13597.28,11957.45 13604.26,11950.47 13625.06,11950.47 13631.41,11944.12 13649.01,11944.12 13649.43,11943.7 13730.41,11943.7 13737.9,11951.19 13833.09,11951.19 13842.68,11960.78 14016.53,11960.78 14020.26,11957.05 14040.51,11957.05 14041.3,11956.26 14041.48,11956.26 v1(14044.32,11953.42) ; v1(13492.93,12745.17) 13487.85,12740.1 13487.85,12736.66 13467.87,12716.68 13446.02,12716.68 13367.19,12637.84 13367.19,12516.42 13539.81,12343.8 13539.81,12209.69 13536.27,12206.15 v1(13536.27,12190.27)
DA11: U1.R7 U2.R7 U23.C2 | length 2409.5
  TOP w4: v1(13298.12,12731.78) 13313.33,12746.99 13368.36,12746.99 13371.39,12743.96 13430.73,12743.96 U23.C2@13446.08,12759.32 ; v1(13306.51,11787.68) 13306.6,11787.59 13306.6,11774.06 13303.43,11770.9 13290.65,11770.9 13285.88,11775.68 13285.88,11796 13295.5,11805.62 13318.92,11805.62 13322.86,11801.68 13322.87,11796.9 13324.21,11795.57 13329.86,11795.57 13334.3,11800.01 13334.3,11824.1 13338.29,11828.09 13361.72,11828.09 13366.38,11832.75 13366.38,11843.92 13364.64,11845.67 13354.66,11845.67 U1.R7@13351.35,11842.36 ; v1(13483.69,12130.48) 13483.69,12128.73 13476.77,12121.81 13476.77,12086.36 13482.53,12080.6 13482.53,12066.04 13492.85,12055.71 13492.85,11976.6 13510.24,11959.21 13510.24,11941.37 13525.73,11925.88 13525.73,11895.24 13525.92,11895.05 13525.92,11840.84 v1(13575.67,11791.07) ; v1(14043.75,11827.24) U2.R7@14058.91,11842.36
  BOTTOM w4: v1(13298.12,12731.78) 13298.12,12728.92 13260.81,12691.6 13260.81,12465.61 13227.17,12431.97 13227.17,12369.7 13224.92,12367.45 13224.92,12195.59 13239.16,12181.35 13365.21,12181.35 13387.9,12158.66 13391.8,12158.66 13391.85,12158.6 13403.45,12158.6 13405.61,12160.76 13423.84,12160.76 13423.91,12160.69 13435.51,12160.69 13435.58,12160.76 13450.08,12160.76 13480.36,12130.48 v1(13483.69,12130.48) ; v1(13306.51,11787.68) 13308.79,11785.39 13319.93,11785.39 13325.65,11791.11 13335.93,11791.11 13341.65,11785.39 13350.31,11785.39 13354.31,11789.39 13354.31,11789.88 13358.31,11793.88 13366.31,11793.88 13370.31,11789.88 13370.31,11789.39 13374.31,11785.39 13379.1,11785.39 13388.78,11795.07 13532.59,11795.07 13536.59,11791.07 v1(13575.67,11791.07) 13578.13,11793.54 13589.8,11793.54 13590.03,11793.77 13620.5,11793.77 13624.73,11789.54 13636.33,11789.54 13640.33,11793.54 13694.72,11793.54 13699.76,11798.57 13853.04,11798.57 13859.84,11791.77 13954.97,11791.77 13956.23,11790.51 13986.9,11790.51 14004.12,11807.74 14024.58,11807.74 14043.75,11826.91 v1(14043.75,11827.24)
DA12: U1.N7 U2.N7 U23.E1 | length 2456.3
  TOP w4: v1(13244.2,12600.11) 13250.91,12600.11 13326.04,12675.24 13395.43,12675.24 13410.14,12689.95 13443.5,12689.95 13467.5,12713.95 13483.33,12713.95 13497.2,12727.82 U23.E1@13509.07,12727.82 ; v1(13294.42,11911.81) 13295.39,11910.84 13345.86,11910.84 U1.N7@13351.35,11905.36 ; v2(13431.77,12112.26) 13431.77,12073.39 13442.53,12062.63 13442.53,12048.64 ; 13442.55,12048.62 13442.55,12046.56 13452.85,12036.26 13452.85,11960.03 13464.02,11948.86 13464.02,11918.29 v1(13474.63,11907.68) ; v1(14035.27,11909.67) 14035.77,11909.17 14055.1,11909.17 U2.N7@14058.91,11905.36
  BOTTOM w4: v1(13244.2,12600.11) 13226.31,12582.22 13226.31,12516.36 13164.12,12454.18 13164.12,12192.7 13184.32,12172.5 13199.92,12156.9 13351.12,12156.9 13382.36,12125.65 13419.76,12125.65 13431.77,12113.64 v2(13431.77,12112.26) ; v1(13294.42,11911.81) 13292.35,11909.75 13292.35,11906.64 13282.76,11897.05 13247.08,11897.05 13240.3,11903.82 13199.49,11903.82 13189.21,11893.55 13189.21,11888.18 13185.21,11884.18 13175.49,11884.18 13172.64,11887.02 13172.64,11919.53 13177.07,11923.95 13236.89,11923.95 13247.12,11913.73 13276.07,11913.73 13292.79,11930.44 13307.06,11930.44 13321.63,11915.87 13381.35,11915.87 13390.72,11906.5 13473.45,11906.5 v1(13474.63,11907.68) 13481.47,11900.84 13602.03,11900.84 13607.04,11895.83 13679,11895.83 13683.95,11900.78 13718.26,11900.78 13720.68,11903.19 13732.28,11903.19 13733.2,11902.27 13761.71,11902.27 13764.83,11899.15 13765.59,11899.15 13770.7,11894.04 13784.13,11894.04 13797.07,11906.98 13892.49,11906.98 13903.71,11918.21 13987.88,11918.21 13987.92,11918.17 13994.82,11918.17 14003.32,11909.67 v1(14035.27,11909.67)
DA13: U1.T3 U2.T3 U23.F3 | length 2098.2
  TOP w4: U1.T3@13225.37,11810.86 13225.37,11796.29 13254.49,11767.18 v1(13254.49,11766.7) ; v1(13523.21,12774.67) 13539.36,12790.81 U23.F3@13540.57,12790.81 ; v1(13558.85,12096.52) 13561.36,12094.01 13561.36,12092.51 13562.85,12091.02 13562.85,12020.14 13606.23,11976.76 13606.23,11953.24 13599.78,11946.79 13599.78,11868.67 13607.27,11861.18 13607.27,11860.31 13611.84,11855.74 13611.84,11844.32 13619.57,11836.59 13619.57,11819.06 13612.92,11812.42 13612.92,11793.73 13622.55,11784.1 13622.55,11754.13 13621.26,11752.83 v1(13621.26,11745.54) ; U2.T3@13932.93,11810.87 13932.93,11796.81 13932.93,11786.78 13928.27,11782.12 13928.27,11770.78 13932.93,11766.12 13932.93,11765.94 13937.41,11761.46 13946.57,11761.46 13951.99,11756.04 13951.99,11750.38 13948.2,11746.59 13939.3,11746.59 v1(13938.16,11747.73)
  BOTTOM w4: v1(13254.49,11766.7) 13254.49,11766.59 13271.85,11749.22 13287.31,11749.22 13301.72,11734.81 13319.32,11734.81 13323.24,11738.73 13380.99,11738.73 13385.02,11734.7 13385.14,11734.58 13495.65,11734.58 13507.92,11746.85 13567.26,11746.85 13568.57,11745.54 v1(13621.26,11745.54) 13624.29,11745.54 13627.03,11742.8 13896.38,11742.8 13901.31,11747.73 v1(13938.16,11747.73) ; v1(13523.21,12774.67) 13523.15,12774.61 13521.89,12773.34 13521.89,12753.81 13474.7,12706.62 13450.5,12706.62 13380.7,12636.83 13380.7,12518.28 13551.52,12347.46 13551.52,12209.57 13549.81,12207.85 13549.81,12196.26 13551.89,12194.17 13551.89,12105.64 13558.85,12098.68 v1(13558.85,12096.52)
DA14: U1.T7 U2.T7 U23.C1 | length 2150.6
  TOP w4: v1(13312.28,12685.91) 13313.59,12685.91 13316.72,12689.04 13318.45,12689.04 13333.36,12703.95 13392.98,12703.95 13402.98,12713.95 13431.44,12713.95 13445.31,12727.82 U23.C1@13446.08,12727.82 ; v1(13313.52,11748.81) 13318.66,11753.95 13333.22,11753.95 13336.19,11756.92 13336.19,11762.58 13332.72,11766.05 13326.51,11766.05 13323.1,11769.47 13323.1,11769.6 13319.29,11773.41 13319.29,11779.07 13324.94,11784.73 13330.6,11784.73 13334.41,11780.92 13340.07,11780.92 13351.35,11792.2 U1.T7@13351.35,11810.86 ; v1(13477.99,12194.49) 13488.35,12184.13 13488.35,12148.4 13497.69,12139.07 13497.69,12124.65 13486.77,12113.73 13486.77,12090.5 13492.53,12084.74 13492.53,12070.31 13502.85,12059.99 13502.85,11982.61 13523.18,11962.28 13523.18,11945.05 13536.6,11931.64 13536.6,11903.85 13535.92,11903.17 13535.92,11847.13 13556.94,11826.11 13562.2,11826.11 13605.31,11783 13605.31,11761.5 v1(13603.35,11759.54) ; v1(14037.2,11792.35) 14041.12,11792.35 14058.91,11810.14 U2.T7@14058.91,11810.87
  BOTTOM w4: v1(13312.28,12685.91) 13302.77,12676.4 13302.77,12500.24 13483.75,12319.27 13483.75,12236.44 13476.64,12229.32 13476.64,12224.97 13476.59,12224.93 13476.59,12202.07 13477.99,12200.68 v1(13477.99,12194.49) ; v1(13313.52,11748.81) 13385.05,11748.81 13389.16,11744.7 13391.62,11744.7 13391.73,11744.58 13455.65,11744.58 13459.65,11748.58 13459.65,11758.86 13463.65,11762.86 13471.65,11762.86 13475.65,11758.86 13475.65,11748.58 13479.65,11744.58 13489.71,11744.58 13502.2,11757.07 13600.89,11757.07 v1(13603.35,11759.54) 13612.3,11759.54 13644.75,11759.54 13649.65,11754.63 13705.11,11754.63 13705.72,11755.24 13894.28,11755.24 13900.76,11761.73 13980.93,11761.73 14011.55,11792.35 v1(14037.2,11792.35)
DA15: U1.M7 U2.M7 U23.E3 | length 1979.1
  TOP w4: v1(13331.27,11945.37) 13325.94,11950.71 13298.17,11950.71 13291.76,11944.3 13291.76,11933.05 13299.19,11925.63 13305.64,11925.63 13309.39,11921.88 13319.44,11921.88 13326.54,11928.98 13335.44,11928.98 13342.54,11921.88 13358.83,11921.88 13363.24,11917.48 13369.78,11917.48 13373.75,11921.44 13373.75,11925.39 13362.3,11936.85 U1.M7@13351.35,11936.85 ; v1(13493.61,12775.34) U23.E3@13509.07,12790.81 ; v1(13531.35,12156.42) 13531.35,12154.37 13534.77,12150.94 13534.77,12085.16 13542.85,12077.08 13542.85,12007.78 13574.31,11976.32 13574.31,11955.3 13585.05,11944.56 v1(13585.05,11929.3) ; v1(13989.59,11935.01) 13991.94,11932.67 14002.04,11932.67 14010.54,11924.17 14046.23,11924.17 U2.M7@14058.91,11936.85
  BOTTOM w4: v1(13331.27,11945.37) 13334.28,11948.38 13405.93,11948.38 13417.69,11936.63 13561.6,11936.63 13568.93,11929.3 v1(13585.05,11929.3) 13591.63,11929.3 13597.23,11923.7 13628.71,11923.7 13629.13,11924.12 13640.72,11924.12 13641.14,11923.7 13749.96,11923.7 13750.47,11923.19 13762.07,11923.19 13766.07,11927.19 13839.4,11927.19 13849.67,11937.46 13984.8,11937.46 13987.25,11935.01 v1(13989.59,11935.01) ; v1@13493.27,12775.34 v1(13493.61,12775.34) 13493.61,12770.36 13475.35,12752.1 13475.35,12739.26 13466.22,12730.13 13444.41,12730.13 13354.89,12640.62 13354.89,12515.44 13357.19,12513.15 13357.19,12512.28 13529.81,12339.66 13529.81,12213.83 13522.27,12206.29 13522.27,12183.53 13522.36,12183.44 13522.36,12176.74 13529.66,12169.44 13529.66,12158.1 v1(13531.35,12156.42)
DBA0: U1.M2 U2.M2 U23.J3 | length 2188.2
  TOP w4: U1.M2@13193.87,11936.85 13211.5,11919.23 13232.74,11919.23 13238.3,11913.67 13248.75,11913.67 13280.44,11881.98 v1(13280.44,11872.19) ; v1(13619.43,12775.52) 13634.73,12790.81 U23.J3@13635.06,12790.81 ; v1(13701.41,11865.78) 13701.55,11865.78 13704.91,11869.13 13727.09,11869.13 13741.18,11883.22 13741.18,11986.58 13752.07,11997.48 13752.52,11997.97 13752.52,12015.23 13750.93,12016.83 13750.93,12086.31 13752.74,12088.12 13752.74,12088.24 13755.2,12090.7 v1(13755.2,12091.29) ; v1(14013.84,11879.63) 14012.15,11877.95 14013.14,11876.96 14013.14,11852.56 14010.4,11849.82 14004.29,11849.82 13999.03,11855.08 13999.03,11865.06 13986.57,11877.51 13986.57,11877.62 13943.03,11921.17 13919.03,11921.17 U2.M2@13903.34,11936.85 ; U2.M2@13903.33,11936.86 U2.M2@13901.43,11936.85 U2.M2@13903.34,11936.85
  BOTTOM w4: v1(13280.44,11872.19) 13291.99,11872.19 13293.43,11870.75 13321.55,11870.75 13321.88,11870.42 13390.05,11870.42 13394.93,11875.3 13445.4,11875.3 13451.37,11869.33 13584.62,11869.33 13588.11,11865.83 v1(13701.41,11865.78) ; v1(13619.43,12775.52) 13619.43,12759.72 13522.59,12662.88 13517.6,12662.88 13496.19,12641.47 13496.19,12568.92 13668.79,12396.31 13668.79,12395.93 13670.79,12393.93 13670.79,12388.35 13672.79,12386.35 13672.79,12204.25 13707.33,12169.71 13707.33,12157.27 13737.7,12126.9 13737.7,12126.73 13746.92,12117.51 13746.92,12115.13 13752.74,12109.32 13752.74,12094.34 13755.2,12091.88 v1(13755.2,12091.29) ; v1@13700.41,11866.78 v1(13701.41,11865.78) ; v1(14013.84,11879.63) 14006.37,11872.17 13892.32,11872.17 13887.5,11876.98 13830.02,11876.98 13814.72,11861.68 13707.11,11861.68 13703.02,11865.78 v1(13701.41,11865.78) v1(13701.41,11865.78)
DBA1: U1.N8 U2.N8 U23.K4 | length 2267.5
  TOP w4: v1(13332.21,11884.42) 13324.83,11891.8 13324.83,11896.97 13328.66,11900.8 13335.05,11900.8 13348.12,11887.73 13360.23,11887.73 13363.53,11891.03 13372.67,11891.03 13375.97,11887.73 13386.24,11887.73 13390.66,11892.15 13390.66,11897.54 U1.N8@13382.85,11905.35 ; U23.K4@13666.56,12822.31 13666.56,12818.06 13677.78,12806.84 v1(13682.03,12806.84) ; v1(13752.88,12161.51) 13789.81,12161.51 13806.52,12144.8 13806.52,12144.27 13820.47,12130.32 13820.47,12031.81 13784.87,11996.22 13784.87,11995.58 13770.27,11980.98 13770.27,11926.47 13759.65,11915.85 13759.65,11894.46 13753.73,11888.55 v1(13753.73,11875.68) ; v1(14075.72,11889.67) 14075.72,11890.67 U2.N8@14090.41,11905.36
  BOTTOM w4: v1(13332.21,11884.42) 13333.1,11885.31 13449.53,11885.31 13455.51,11879.33 13591.44,11879.33 13594.94,11875.83 13687.28,11875.83 13692.23,11880.78 13708.02,11880.78 13715.63,11873.17 13742.55,11873.17 13743.81,11874.43 13752.48,11874.43 v1(13753.73,11875.68) 13757.38,11872.03 13805.72,11872.03 13820.68,11886.98 13899.93,11886.98 13900.8,11886.11 13998.43,11886.11 14006.55,11894.23 14050.6,11894.23 14072.29,11915.92 14088.72,11915.92 14094.91,11909.73 14094.91,11843.05 14082.53,11830.67 14065.03,11830.67 14052.53,11843.17 14052.53,11869.69 14072.45,11889.61 14075.66,11889.61 v1(14075.72,11889.67) ; v1(13682.03,12806.84) 13682.03,12795.43 13670.57,12783.96 13667.82,12781.22 13667.82,12768.79 13670.57,12766.05 13670.57,12747.3 13669.23,12745.97 13669.23,12745.91 13563.43,12640.12 13563.43,12561.86 13720.79,12404.5 13720.79,12244.57 13746.97,12218.39 13746.97,12167.43 v1(13752.88,12161.51)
